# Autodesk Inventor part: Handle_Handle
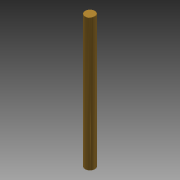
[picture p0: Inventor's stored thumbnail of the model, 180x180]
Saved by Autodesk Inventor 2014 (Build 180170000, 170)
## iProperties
Created: 2014-03
Part Number: Handle_Handle
Material: Generic
Document SubType Name: Modeling
Designer: Beast
Density: 1 g/cm^3
Appearance: Brass - Satin
Author: Beast
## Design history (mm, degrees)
sketch "Sketch1"
  geometry: C1 r 4.763 at (0, 0); 1 further point
  constraints: 1 centre point, 1 coincident
  dimensions: "d0" = 9.525 diameter of C1
extrude "Extrusion1" new body sketch "Sketch1" distance "d1" = 127; taper "d2" = 0 deg
chamfer "Chamfer1" distance "d3" = 0.254; stored, may be unused: second distance "d4" = 3.175, angle "d5" = 45 deg
chamfer "Chamfer2" distance "d6" = 0.254; stored, may be unused: second distance "d7" = 3.175, angle "d8" = 45 deg
body "Solid1"
